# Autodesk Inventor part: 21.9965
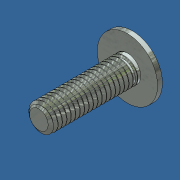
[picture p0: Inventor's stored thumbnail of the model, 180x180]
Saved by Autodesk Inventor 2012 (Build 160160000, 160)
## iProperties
Created: 2009-08
Part Number: 21.9965
Document SubType Name: Modeling
Designer: Administrator
Density: 7.85 g/cm^3
Material: Steel
Description: M6x20 BUTTON HEAD FLANGE SCREW
Mass: 5.50826 g
Surface Area: 9.67967 cm^2
Volume: 0.701689 cm^3
Vendor: S
Title: M6x20 Button Head Flange Screw
Author: Administrator
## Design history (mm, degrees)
feature "Base1"
body "Solid1"
